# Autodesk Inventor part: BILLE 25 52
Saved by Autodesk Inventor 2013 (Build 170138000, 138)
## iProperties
Created: 2012-12
Part Number: BILLE 25 52
Material: Générique
Document SubType Name: Modeling
Designer: jost thierry
Density: 1 g/cm^3
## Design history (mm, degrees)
node "BILLE 25 521"
node "BILLE 25 52"
node "Base1"
